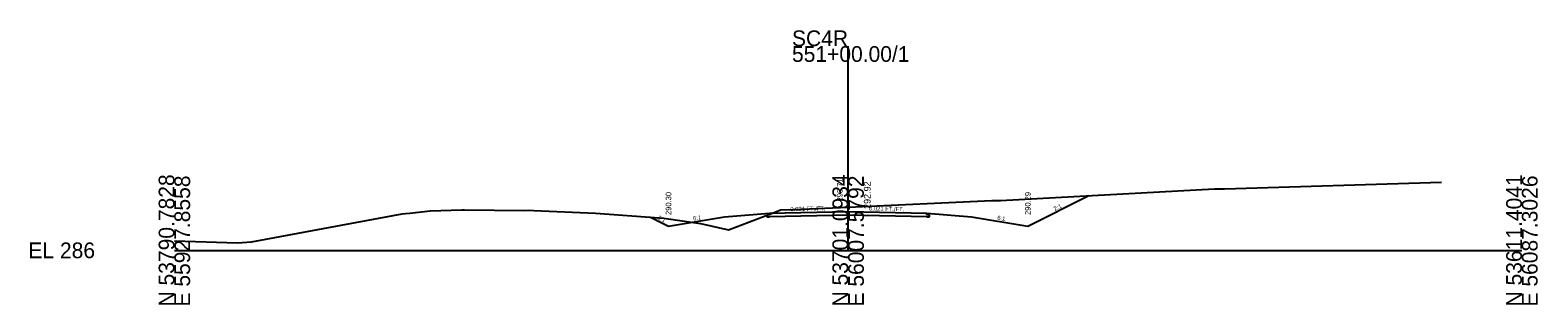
# Model space of a CAD drawing. Extents: x 9740 to 17409, y 8856 to 28416.
# Drawn here: x 12740.2 to 13008.7, y 11861.7 to 11910.6 of the extents above; entities that cross this region are included whole.
import ezdxf

# ---------------------------------------------------------------- set-up
doc = ezdxf.new("R2010")
doc.units = 0
for name, color, linetype in [('Level 10', 7, 'Continuous'), ('Level 11', 7, 'Continuous'), ('Level 12', 7, 'Continuous'), ('Level 32', 7, 'Continuous'), ('Level 33', 7, 'Continuous'), ('Level 59', 7, 'Continuous'), ('Level 6', 7, 'Continuous'), ('Level 60', 7, 'Continuous'), ('Level 63', 7, 'Continuous'), ('Level 7', 7, 'Continuous')]:
    doc.layers.add(name, color=color, linetype=linetype)

msp = doc.modelspace()

# ---------------------------------------------------------------- linework, layer by layer
at = {"layer": 'Level 11'}
for p, q in [((12871.85, 11877.71), (12871.35, 11877.7)), ((12871.35, 11877.7), (12871.35, 11877.36)), ((12871.35, 11877.36), (12871.85, 11877.37)), ((12871.85, 11878.01), (12871.85, 11877.71)), ((12899.85, 11877.71), (12899.85, 11878.01)), ((12900.35, 11877.7), (12899.85, 11877.71)), ((12899.85, 11877.37), (12900.35, 11877.36)), ((12900.35, 11877.36), (12900.35, 11877.7))]:
    msp.add_line(p, q, dxfattribs=at)
at = {"layer": 'Level 12'}
for p, q in [((12885.85, 11877.66), (12871.85, 11877.37)), ((12899.85, 11877.37), (12885.85, 11877.66))]:
    msp.add_line(p, q, dxfattribs=at)
at = {"layer": 'Level 59'}
for p, q in [((12871.85, 11878.01), (12885.85, 11878.3)), ((12885.85, 11878.3), (12899.85, 11878.01))]:
    msp.add_line(p, q, dxfattribs=at)
at = {"layer": 'Level 6'}
for p, q in [((12863.85, 11877.34), (12871.85, 11878.01)), ((12899.85, 11878.01), (12907.85, 11877.34))]:
    msp.add_line(p, q, dxfattribs=at)
at = {"layer": 'Level 60'}
for p, q in [((12952.88, 11882.33), (12991.53, 11883.49)), ((12885.85, 11879.09), (12911.42, 11880.27)), ((12911.42, 11880.27), (12913.01, 11880.26)), ((12913.01, 11880.26), (12951.12, 11882.33)), ((12951.12, 11882.33), (12952.88, 11882.33)), ((12779.58, 11872.89), (12806.4, 11877.86)), ((12806.4, 11877.86), (12807.04, 11877.92)), ((12807.04, 11877.92), (12807.76, 11878.02)), ((12807.76, 11878.02), (12811.42, 11878.39)), ((12811.42, 11878.39), (12817.06, 11878.57)), ((12817.06, 11878.57), (12817.54, 11878.58)), ((12817.54, 11878.58), (12828.12, 11878.49)), ((12828.12, 11878.49), (12829.03, 11878.5)), ((12829.03, 11878.5), (12829.89, 11878.49)), ((12829.89, 11878.49), (12840.85, 11878.01)), ((12840.85, 11878.01), (12852.18, 11877.17)), ((12864.55, 11875.05), (12873.29, 11878.35)), ((12873.29, 11878.35), (12873.8, 11878.59)), ((12873.8, 11878.59), (12876.18, 11878.64)), ((12876.18, 11878.64), (12885.85, 11879.09)), ((12852.18, 11877.17), (12853.02, 11877.13)), ((12853.02, 11877.13), (12853.44, 11877.02)), ((12853.44, 11877.02), (12859.16, 11876.22)), ((12859.16, 11876.22), (12859.57, 11876.13)), ((12859.57, 11876.13), (12864.55, 11875.05)), ((12765.85, 11873.1), (12777.07, 11872.7)), ((12777.07, 11872.7), (12779.58, 11872.89))]:
    msp.add_line(p, q, dxfattribs=at)
at = {"layer": 'Level 63'}
for p, q in [((12885.85, 11871.38), (12885.85, 11907.72)), ((12765.85, 11871.38), (12885.85, 11871.38)), ((12885.85, 11871.38), (13005.85, 11871.38))]:
    msp.add_line(p, q, dxfattribs=at)
at = {"layer": 'Level 7'}
for p, q in [((12917.85, 11875.68), (12928.74, 11881.12)), ((12850.63, 11877.28), (12853.85, 11875.68)), ((12853.85, 11875.68), (12863.85, 11877.34)), ((12907.85, 11877.34), (12917.85, 11875.68))]:
    msp.add_line(p, q, dxfattribs=at)

# ---------------------------------------------------------------- texts
at = {"layer": 'Level 10'}
msp.add_text('293.71', height=1, rotation=90, dxfattribs=at).set_placement((12884.85, 11880.09))
at = {"layer": 'Level 32'}
for s, rotation, p in [('2:1', 333.435, (12851.85, 11876.96)), ('6:1', 9.4623, (12858.29, 11876.67)), ('0.021 FT./FT.', 1.1916, (12875.56, 11878.34)), ('0.021 FT./FT.', 358.8084, (12889.57, 11878.47)), ('6:1', 350.5377, (12912.37, 11876.84)), ('2:1', 26.5651, (12922.68, 11878.37))]:
    msp.add_text(s, height=0.75, rotation=rotation, dxfattribs=at).set_placement(p)
at = {"layer": 'Level 33'}
for s, p in [('290.30', (12854.35, 11877.68)), ('290.29', (12918.35, 11877.68))]:
    msp.add_text(s, height=1, rotation=90, dxfattribs=at).set_placement(p)
at = {"layer": 'Level 59'}
msp.add_text(' 292.92', height=1.2, rotation=90, dxfattribs=at).set_placement((12889.85, 11878.3))
at = {"layer": 'Level 63'}
for s, p in [('SC4R', (12875.85, 11907.72)), ('551+00.00/1', (12875.85, 11904.92)), ('EL 286', (12739.85, 11869.98))]:
    msp.add_text(s, height=2.8, dxfattribs=at).set_placement(p)
for s, p in [('N 53790.7828', (12765.85, 11861.38)), ('E 55927.8558', (12768.65, 11861.38)), ('N 53701.0934', (12885.85, 11861.38)), ('E 56007.5792', (12888.65, 11861.38)), ('N 53611.4041', (13005.85, 11861.38)), ('E 56087.3026', (13008.65, 11861.38))]:
    msp.add_text(s, height=2.8, rotation=90, dxfattribs=at).set_placement(p)

doc.saveas('drawing.dxf')
